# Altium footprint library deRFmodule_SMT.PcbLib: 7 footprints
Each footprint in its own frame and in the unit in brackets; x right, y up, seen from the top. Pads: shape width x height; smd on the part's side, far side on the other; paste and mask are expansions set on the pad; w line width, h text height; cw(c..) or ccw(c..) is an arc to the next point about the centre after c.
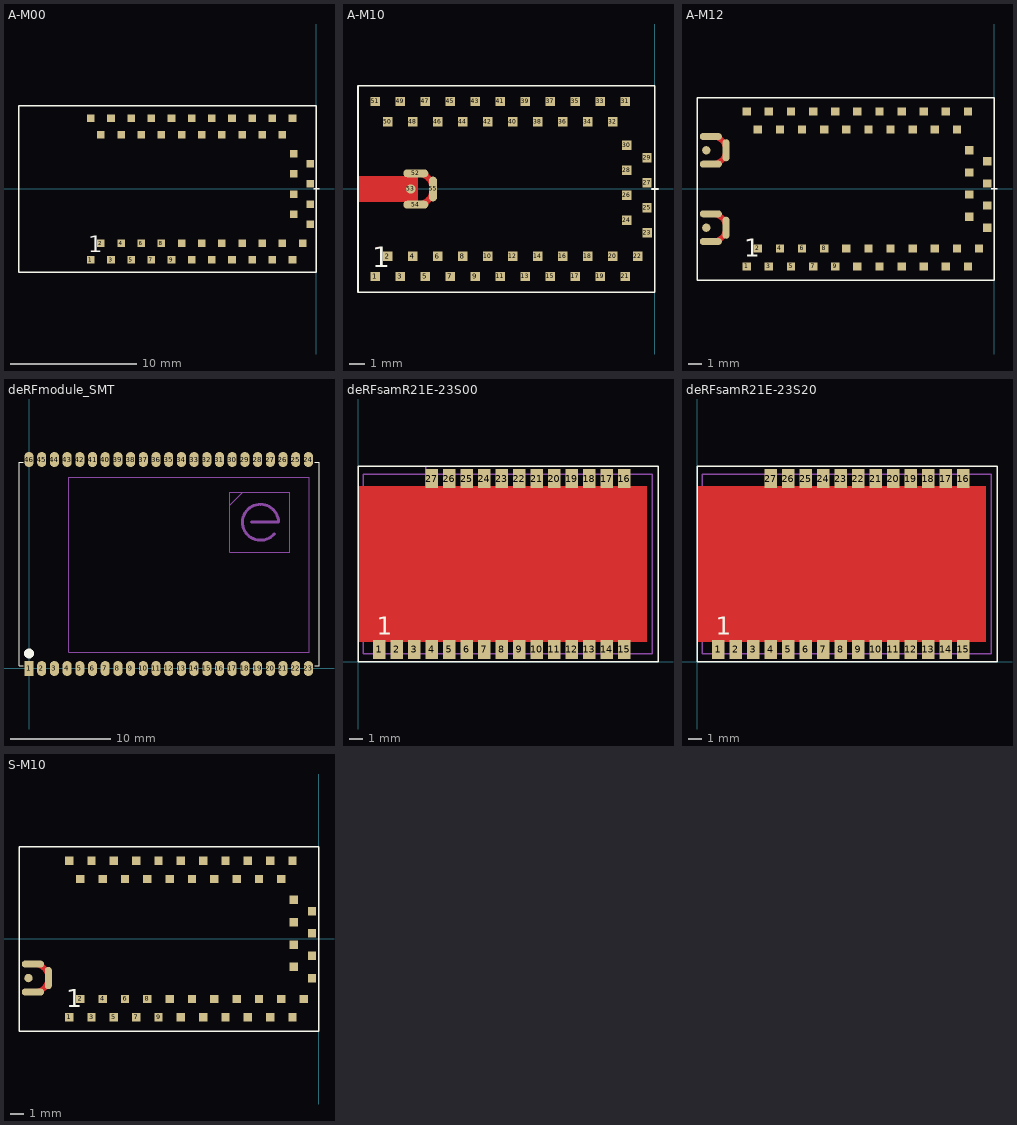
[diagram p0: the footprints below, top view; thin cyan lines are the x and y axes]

## A-M00 [mm] "Footprint deRFmega128-22M00"
height 3
pads (51):
  rect 0.6x0.6 smd paste+0: 1(-17.9,-5.6) 2(-17.1,-4.3) 3(-16.3,-5.6) 4(-15.5,-4.3) 5(-14.7,-5.6) 6(-13.9,-4.3) 7(-13.1,-5.6) 8(-12.3,-4.3) 9(-11.5,-5.6) 10(-10.7,-4.3) 11(-9.9,-5.6) 12(-9.1,-4.3) 13(-8.3,-5.6) 14(-7.5,-4.3) 15(-6.7,-5.6) 16(-5.9,-4.3) 17(-5.1,-5.6) 18(-4.3,-4.3) 19(-3.5,-5.6) 20(-2.7,-4.3) 21(-1.9,-5.6) 22(-1.1,-4.3) 23(-0.5,-2.8) 24(-1.8,-2) 25(-0.5,-1.2) 26(-1.8,-0.4) 27(-0.5,0.4) 28(-1.8,1.2) 29(-0.5,2) 30(-1.8,2.8) 31(-1.9,5.6) 32(-2.7,4.3) 33(-3.5,5.6) 34(-4.3,4.3) 35(-5.1,5.6) 36(-5.9,4.3) 37(-6.7,5.6) 38(-7.5,4.3) 39(-8.3,5.6) 40(-9.1,4.3) 41(-9.9,5.6) 42(-10.7,4.3) 43(-11.5,5.6) 44(-12.3,4.3) 45(-13.1,5.6) 46(-13.9,4.3) 47(-14.7,5.6) 48(-15.5,4.3) 49(-16.3,5.6) 50(-17.1,4.3) 51(-17.9,5.6)
Top Overlay:
  lines w0.1: -0.2,0 0.2,0 ; -23.6,-6.6 0,-6.6 0,6.6 -23.6,6.6 -23.6,-6.6
  text "1" at -18.1,-5 h1.3
3D body: height 1, standoff 0, extent -23.6,-6.6 0,6.6
3D body: height 3, standoff 0.5, extent -18.6,-5.7 -0.4,5.7

## A-M10 [mm] "Footprint deRFmega128-22M10"
height 3
pads (55):
  rect 0.6x0.6 smd paste+0: 1(-17.9,-5.6) 2(-17.1,-4.3) 3(-16.3,-5.6) 4(-15.5,-4.3) 5(-14.7,-5.6) 6(-13.9,-4.3) 7(-13.1,-5.6) 8(-12.3,-4.3) 9(-11.5,-5.6) 10(-10.7,-4.3) 11(-9.9,-5.6) 12(-9.1,-4.3) 13(-8.3,-5.6) 14(-7.5,-4.3) 15(-6.7,-5.6) 16(-5.9,-4.3) 17(-5.1,-5.6) 18(-4.3,-4.3) 19(-3.5,-5.6) 20(-2.7,-4.3) 21(-1.9,-5.6) 22(-1.1,-4.3) 23(-0.5,-2.8) 24(-1.8,-2) 25(-0.5,-1.2) 26(-1.8,-0.4) 27(-0.5,0.4) 28(-1.8,1.2) 29(-0.5,2) 30(-1.8,2.8) 31(-1.9,5.6) 32(-2.7,4.3) 33(-3.5,5.6) 34(-4.3,4.3) 35(-5.1,5.6) 36(-5.9,4.3) 37(-6.7,5.6) 38(-7.5,4.3) 39(-8.3,5.6) 40(-9.1,4.3) 41(-9.9,5.6) 42(-10.7,4.3) 43(-11.5,5.6) 44(-12.3,4.3) 45(-13.1,5.6) 46(-13.9,4.3) 47(-14.7,5.6) 48(-15.5,4.3) 49(-16.3,5.6) 50(-17.1,4.3) 51(-17.9,5.6)
  oval 1.6x0.5 smd paste-0.15 mask+0.05: 52(-15.3,1) 54(-15.3,-1)
  round 0.6 smd paste+0 mask+0.05: 53(-15.625,0)
  oval 0.5x1.6 smd paste-0.15 mask+0.05: 55(-14.2,0)
Top Layer:
  pour cut-out: -19,-0.825 -15.175,-0.825 -15.175,0.825 -19,0.825
  lines w0.4: -15.2,-1 ccw(c-15.2,0) -15.2,1
Top Overlay:
  lines w0.1: -0.2,0 0.2,0 ; -19,-6.6 0,-6.6 0,6.6 -19,6.6 -19,-6.6
  text "1" at -18.1,-5 h1.3
Top Solder:
  lines w0.5: -15.2,-1 ccw(c-15.2,0) -15.2,1
3D body: height 1, standoff 0, extent -19,-6.6 0,6.6
3D body: height 3, standoff 0.5, extent -18.6,-5.7 -0.4,5.7

## A-M12 [mm] "Footprint deRFmega128-22M12"
height 3
pads (59):
  rect 0.6x0.6 smd paste+0: 1(-17.9,-5.6) 2(-17.1,-4.3) 3(-16.3,-5.6) 4(-15.5,-4.3) 5(-14.7,-5.6) 6(-13.9,-4.3) 7(-13.1,-5.6) 8(-12.3,-4.3) 9(-11.5,-5.6) 10(-10.7,-4.3) 11(-9.9,-5.6) 12(-9.1,-4.3) 13(-8.3,-5.6) 14(-7.5,-4.3) 15(-6.7,-5.6) 16(-5.9,-4.3) 17(-5.1,-5.6) 18(-4.3,-4.3) 19(-3.5,-5.6) 20(-2.7,-4.3) 21(-1.9,-5.6) 22(-1.1,-4.3) 23(-0.5,-2.8) 24(-1.8,-2) 25(-0.5,-1.2) 26(-1.8,-0.4) 27(-0.5,0.4) 28(-1.8,1.2) 29(-0.5,2) 30(-1.8,2.8) 31(-1.9,5.6) 32(-2.7,4.3) 33(-3.5,5.6) 34(-4.3,4.3) 35(-5.1,5.6) 36(-5.9,4.3) 37(-6.7,5.6) 38(-7.5,4.3) 39(-8.3,5.6) 40(-9.1,4.3) 41(-9.9,5.6) 42(-10.7,4.3) 43(-11.5,5.6) 44(-12.3,4.3) 45(-13.1,5.6) 46(-13.9,4.3) 47(-14.7,5.6) 48(-15.5,4.3) 49(-16.3,5.6) 50(-17.1,4.3) 51(-17.9,5.6)
  oval 1.6x0.5 smd paste-0.15 mask+0.05: 52(-20.5,3.8) 54(-20.5,1.8) 56(-20.5,-1.8) 58(-20.5,-3.8)
  round 0.6 smd paste+0 mask+0.05: 53(-20.825,2.8) 57(-20.825,-2.8)
  oval 0.5x1.6 smd paste-0.15 mask+0.05: 55(-19.4,2.8) 59(-19.4,-2.8)
Top Layer:
  lines w0.4: -20.4,-3.8 ccw(c-20.4,-2.8) -20.4,-1.8 ; -20.4,1.8 ccw(c-20.4,2.8) -20.4,3.8
Top Overlay:
  lines w0.1: -0.2,0 0.2,0 ; -21.5,-6.6 -21.5,6.6 0,6.6 0,-6.6 -21.5,-6.6
  text "1" at -18.1,-4.9 h1.3
3D body: height 3, standoff 0.5, extent -21.1,-5.7 -0.4,5.7
3D body: height 1, standoff 0, extent -21.5,-6.6 0,6.6

## deRFmodule_SMT [mm]
pads (46):
  rect 0.9x1.5 smd: 1(0,0)
  oval 0.9x1.5 smd: 2(1.27,0) 3(2.54,0) 4(3.81,0) 5(5.08,0) 6(6.35,0) 7(7.62,0) 8(8.89,0) 9(10.16,0) 10(11.43,0) 11(12.7,0) 12(13.97,0) 13(15.24,0) 14(16.51,0) 15(17.78,0) 16(19.05,0) 17(20.32,0) 18(21.59,0) 19(22.86,0) 20(24.13,0) 21(25.4,0) 22(26.67,0) 23(27.94,0) 24(27.94,20.9) 25(26.67,20.9) 26(25.4,20.9) 27(24.13,20.9) 28(22.86,20.9) 29(21.59,20.9) 30(20.32,20.9) 31(19.05,20.9) 32(17.78,20.9) 33(16.51,20.9) 34(15.24,20.9) 35(13.97,20.9) 36(12.7,20.9) 37(11.43,20.9) 38(10.16,20.9) 39(8.89,20.9) 40(7.62,20.9) 41(6.35,20.9) 42(5.08,20.9) 43(3.81,20.9) 44(2.54,20.9) 45(1.27,20.9) 46(0,20.9)
Top Overlay:
  circle w0.5: c0,1.5 r0.25
  lines w0.1: -0.6,0.25 -1,0.25 -1,20.65 -0.6,20.65 ; 28.6,0.25 29,0.25 29,20.65 28.6,20.65
Mechanical 3:
  lines w0.1: 20.05,16.325 21.35,17.625 ; 3.95,1.625 28,1.625 28,19.125 3.95,19.125 3.95,1.625 ; 20.05,11.625 20.05,17.625 26.05,17.625 26.05,11.625 20.05,11.625
  lines w0.3: 22.25,14.625 24.95,14.625 ccw(c23.15,14.625) 24.529,13.468
  text "www.dresden-elektronik.de" at 5.35,3.325 h1.2

## deRFsamR21E-23S00 [mm]
height 2.5
pads (27):
  rrect5% 0.9x1.4 smd paste+0 mask+0.075: 1(1.55,0.9) 2(2.82,0.9) 3(4.09,0.9) 4(5.36,0.9) 5(6.63,0.9) 6(7.9,0.9) 7(9.17,0.9) 8(10.44,0.9) 9(11.71,0.9) 10(12.98,0.9) 11(14.25,0.9) 12(15.52,0.9) 13(16.79,0.9) 14(18.06,0.9) 15(19.33,0.9) 16(19.33,13.3) 17(18.06,13.3) 18(16.79,13.3) 19(15.52,13.3) 20(14.25,13.3) 21(12.98,13.3) 22(11.71,13.3) 23(10.44,13.3) 24(9.17,13.3) 25(7.9,13.3) 26(6.63,13.3) 27(5.36,13.3)
Top Layer:
  pour cut-out: 20.975,12.75 0,12.75 0,1.45 20.975,1.45
Top Overlay:
  lines w0.1: 0,0 21.775,0 21.775,14.2 0,14.2 0,0
  text "1" at 1.357,1.969 h1.3
Mechanical 3:
  lines w0.1: 0,7.1 4.9,7.1 4.9,14.2
  text "NO COPPER AREA / (ALL LAYERS)" at 0.175,8.825 h0.5
  text "NO COPPER AREA / (TOP LAYER)" at 9,7 h0.5
Mechanical 15:
  lines w0.1: 0.375,0.6 21.37,0.6 21.37,13.6 0.375,13.6 0.375,0.6
3D body: height 2.55, standoff 0.01, extent 0.37,0.6 21.37,13.6

## deRFsamR21E-23S20 [mm]
height 2.5
pads (27):
  rrect5% 0.9x1.4 smd paste+0 mask+0.075: 1(1.55,0.9) 2(2.82,0.9) 3(4.09,0.9) 4(5.36,0.9) 5(6.63,0.9) 6(7.9,0.9) 7(9.17,0.9) 8(10.44,0.9) 9(11.71,0.9) 10(12.98,0.9) 11(14.25,0.9) 12(15.52,0.9) 13(16.79,0.9) 14(18.06,0.9) 15(19.33,0.9) 16(19.33,13.3) 17(18.06,13.3) 18(16.79,13.3) 19(15.52,13.3) 20(14.25,13.3) 21(12.98,13.3) 22(11.71,13.3) 23(10.44,13.3) 24(9.17,13.3) 25(7.9,13.3) 26(6.63,13.3) 27(5.36,13.3)
Top Layer:
  pour cut-out: 20.975,12.75 0,12.75 0,1.45 20.975,1.45
Top Overlay:
  lines w0.1: 0,0 21.775,0 21.775,14.2 0,14.2 0,0
  text "1" at 1.357,1.969 h1.3
Mechanical 3:
  text "NO COPPER AREA / (TOP LAYER)" at 9,7 h0.5
Mechanical 15:
  lines w0.1: 0.375,0.6 21.37,0.6 21.37,13.6 0.375,13.6 0.375,0.6
3D body: height 2.55, standoff 0.01, extent 0.37,0.6 21.37,13.6

## S-M10 [mm] "Footprint deRFsam3-xxM10-x"
height 3
pads (55):
  rect 0.6x0.6 smd paste+0: 1(-17.9,-5.6) 2(-17.1,-4.3) 3(-16.3,-5.6) 4(-15.5,-4.3) 5(-14.7,-5.6) 6(-13.9,-4.3) 7(-13.1,-5.6) 8(-12.3,-4.3) 9(-11.5,-5.6) 10(-10.7,-4.3) 11(-9.9,-5.6) 12(-9.1,-4.3) 13(-8.3,-5.6) 14(-7.5,-4.3) 15(-6.7,-5.6) 16(-5.9,-4.3) 17(-5.1,-5.6) 18(-4.3,-4.3) 19(-3.5,-5.6) 20(-2.7,-4.3) 21(-1.9,-5.6) 22(-1.1,-4.3) 23(-0.5,-2.8) 24(-1.8,-2) 25(-0.5,-1.2) 26(-1.8,-0.4) 27(-0.5,0.4) 28(-1.8,1.2) 29(-0.5,2) 30(-1.8,2.8) 31(-1.9,5.6) 32(-2.7,4.3) 33(-3.5,5.6) 34(-4.3,4.3) 35(-5.1,5.6) 36(-5.9,4.3) 37(-6.7,5.6) 38(-7.5,4.3) 39(-8.3,5.6) 40(-9.1,4.3) 41(-9.9,5.6) 42(-10.7,4.3) 43(-11.5,5.6) 44(-12.3,4.3) 45(-13.1,5.6) 46(-13.9,4.3) 47(-14.7,5.6) 48(-15.5,4.3) 49(-16.3,5.6) 50(-17.1,4.3) 51(-17.9,5.6)
  oval 1.6x0.5 smd paste-0.15 mask+0.05: 52(-20.5,-1.8) 54(-20.5,-3.8)
  round 0.6 smd paste+0 mask+0.05: 53(-20.825,-2.8)
  oval 0.5x1.6 smd paste-0.15 mask+0.05: 55(-19.4,-2.8)
Top Layer:
  lines w0.4: -20.4,-3.8 ccw(c-20.4,-2.8) -20.4,-1.8
Top Overlay:
  lines w0.1: -21.5,-6.6 -21.5,6.6 0,6.6 0,-6.6 -21.5,-6.6
  text "1" at -18.1,-4.9 h1.3
Top Solder:
  lines w0.5: -20.4,-3.8 ccw(c-20.4,-2.8) -20.4,-1.8
3D body: height 3, standoff 0.5, extent -21.1,-5.7 -0.4,5.7
3D body: height 1, standoff 0, extent -21.5,-6.6 0,6.6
